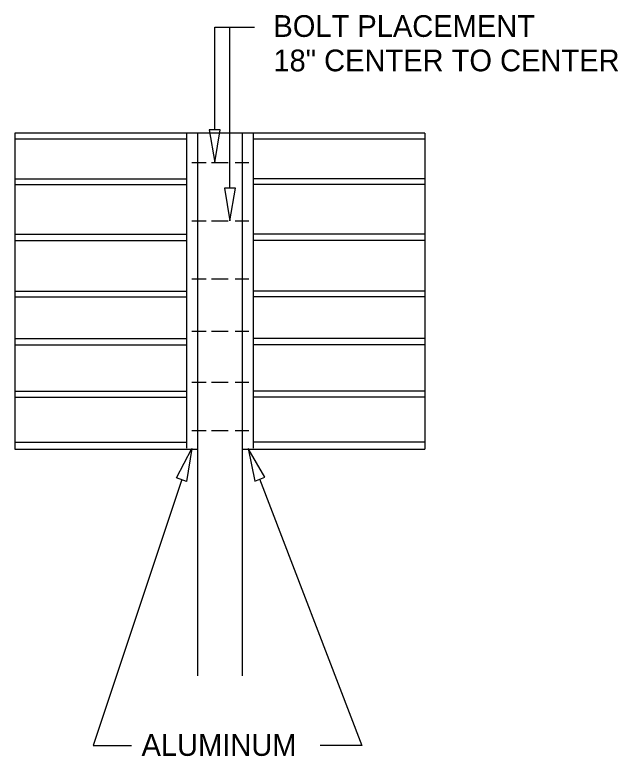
# Model space of a CAD drawing. Extents: x 126.99 to 133.44, y 121.5 to 131.07.
# Drawn here: x 129.197 to 130.863, y 125.412 to 127.459 of the extents above; entities that cross this region are included whole.
import ezdxf

# ---------------------------------------------------------------- set-up
doc = ezdxf.new("R2010")
doc.units = 0
for name, color, linetype in [('DETL-DIMS', 7, 'Continuous'), ('DETL-LINE', 7, 'Continuous'), ('DETL-NOTE', 7, 'Continuous')]:
    doc.layers.add(name, color=color, linetype=linetype)

msp = doc.modelspace()

# ---------------------------------------------------------------- linework, layer by layer
at = {"layer": 'DETL-DIMS'}
for p, q in [((129.7489, 127.1408), (129.7489, 127.4248)), ((129.7489, 127.4248), (129.8589, 127.4248)), ((129.7909, 126.9798), (129.7909, 127.4248)), ((129.6579, 126.1758), (129.4129, 125.4408)), ((129.8729, 126.1778), (130.1549, 125.4408)), ((129.4129, 125.4408), (129.5189, 125.4408)), ((130.1549, 125.4408), (130.0399, 125.4408))]:
    msp.add_line(p, q, dxfattribs=at)
for points in [[(129.7639, 127.1408), (129.7339, 127.1408), (129.7489, 127.0508)], [(129.8059, 126.9798), (129.7759, 126.9798), (129.7909, 126.8898)], [(129.6709, 126.1698), (129.6429, 126.1798), (129.6859, 126.2608)], [(129.8599, 126.1708), (129.8869, 126.1818), (129.8409, 126.2608)]]:
    msp.add_lwpolyline(points, close=True, dxfattribs=at)
at = {"layer": 'DETL-LINE'}
for p, q in [((130.3289, 127.1318), (129.1969, 127.1318)), ((129.1969, 127.1318), (129.1969, 126.2598)), ((129.6709, 127.1298), (129.6709, 126.2618)), ((129.7009, 127.1298), (129.7009, 126.2208)), ((129.8249, 127.1298), (129.8249, 126.2208)), ((129.8549, 127.1298), (129.8549, 126.2618)), ((130.3289, 127.1318), (130.3289, 126.2598)), ((129.6709, 127.1158), (129.1969, 127.1158)), ((130.3289, 127.1158), (129.8549, 127.1158)), ((129.6859, 127.0508), (129.7249, 127.0508)), ((129.7399, 127.0508), (129.7859, 127.0508)), ((129.8049, 127.0508), (129.8429, 127.0508)), ((129.1969, 127.0058), (129.6709, 127.0058)), ((130.3289, 127.0058), (129.8549, 127.0058)), ((129.1969, 126.9898), (129.6709, 126.9898)), ((130.3289, 126.9898), (129.8549, 126.9898)), ((129.6859, 126.8898), (129.7249, 126.8898)), ((129.7399, 126.8898), (129.7859, 126.8898)), ((129.8049, 126.8898), (129.8429, 126.8898)), ((129.1969, 126.8528), (129.6709, 126.8528)), ((130.3289, 126.8528), (129.8549, 126.8528)), ((129.1969, 126.8358), (129.6709, 126.8358)), ((130.3289, 126.8358), (129.8549, 126.8358)), ((129.6859, 126.7298), (129.7249, 126.7298)), ((129.7399, 126.7298), (129.7859, 126.7298)), ((129.8049, 126.7298), (129.8429, 126.7298)), ((129.1969, 126.6958), (129.6709, 126.6958)), ((130.3289, 126.6958), (129.8549, 126.6958)), ((129.1969, 126.6798), (129.6709, 126.6798)), ((130.3289, 126.6798), (129.8549, 126.6798)), ((129.6859, 126.5848), (129.7249, 126.5848)), ((129.7399, 126.5848), (129.7859, 126.5848)), ((129.8049, 126.5848), (129.8429, 126.5848)), ((129.1969, 126.5648), (129.6709, 126.5648)), ((130.3289, 126.5648), (129.8549, 126.5648)), ((129.1969, 126.5478), (129.6709, 126.5478)), ((130.3289, 126.5478), (129.8549, 126.5478)), ((129.6859, 126.4448), (129.7249, 126.4448)), ((129.7399, 126.4448), (129.7859, 126.4448)), ((129.8049, 126.4448), (129.8429, 126.4448)), ((129.1969, 126.4198), (129.6709, 126.4198)), ((130.3289, 126.4198), (129.8549, 126.4198)), ((129.1969, 126.4028), (129.6709, 126.4028)), ((130.3289, 126.4028), (129.8549, 126.4028)), ((129.6859, 126.3108), (129.7249, 126.3108)), ((129.7399, 126.3108), (129.7859, 126.3108)), ((129.8049, 126.3108), (129.8429, 126.3108)), ((129.1969, 126.2788), (129.6709, 126.2788)), ((130.3289, 126.2788), (129.8549, 126.2788)), ((129.1969, 126.2598), (129.7009, 126.2598)), ((129.8249, 126.2598), (130.3289, 126.2598)), ((129.7009, 126.2208), (129.7009, 125.6338)), ((129.8249, 126.2208), (129.8249, 125.6338))]:
    msp.add_line(p, q, dxfattribs=at)

# ---------------------------------------------------------------- texts
at = {"layer": 'DETL-NOTE'}
for s, p in [('BOLT PLACEMENT ', (129.9109, 127.3978)), ('18" CENTER TO CENTER', (129.9109, 127.3028)), ('ALUMINUM', (129.5468, 125.4125))]:
    msp.add_text(s, height=0.06, dxfattribs=at).set_placement(p)

doc.saveas('drawing.dxf')
